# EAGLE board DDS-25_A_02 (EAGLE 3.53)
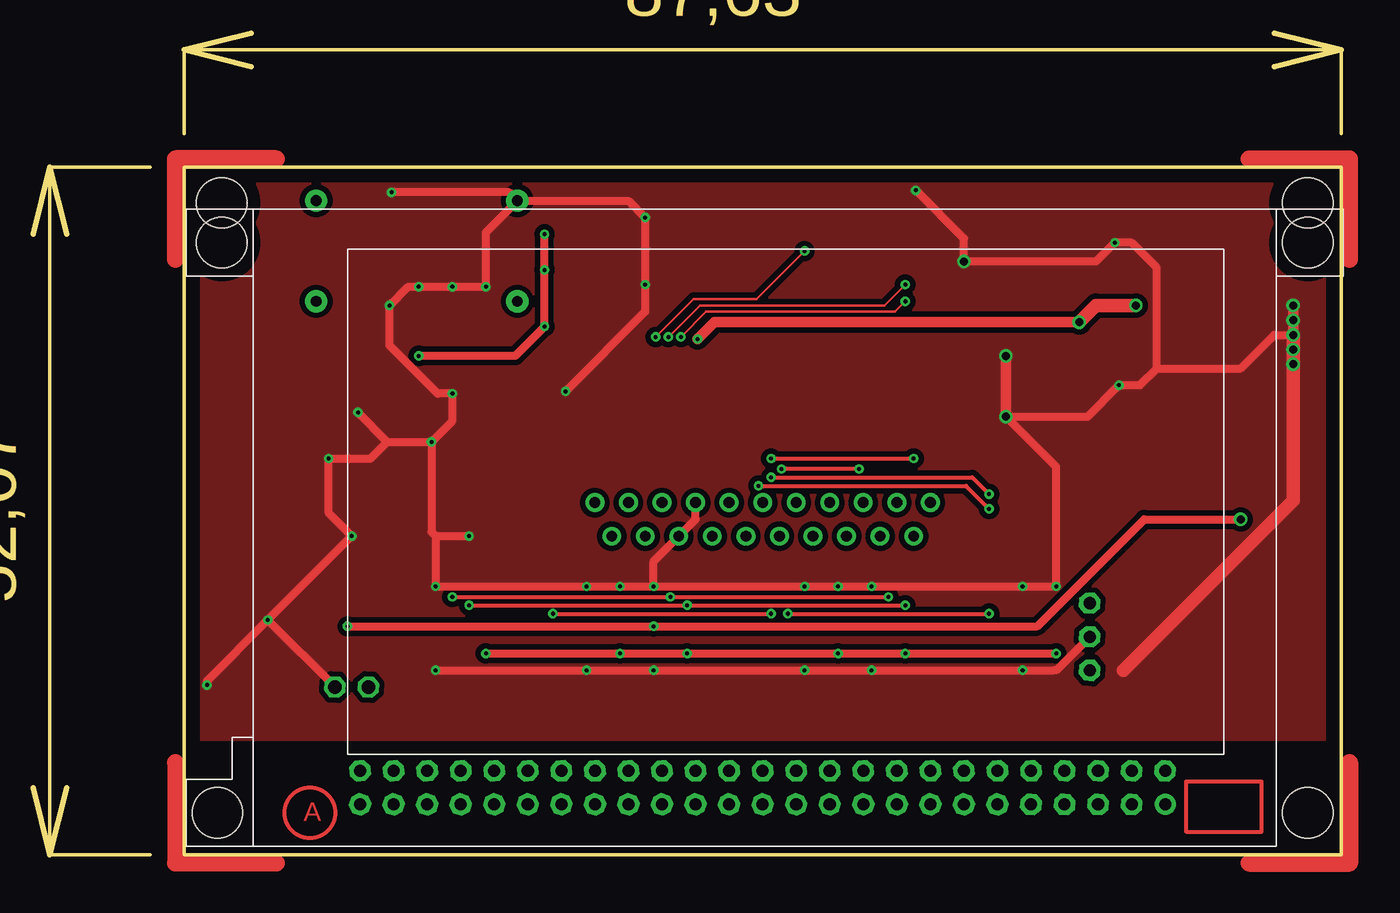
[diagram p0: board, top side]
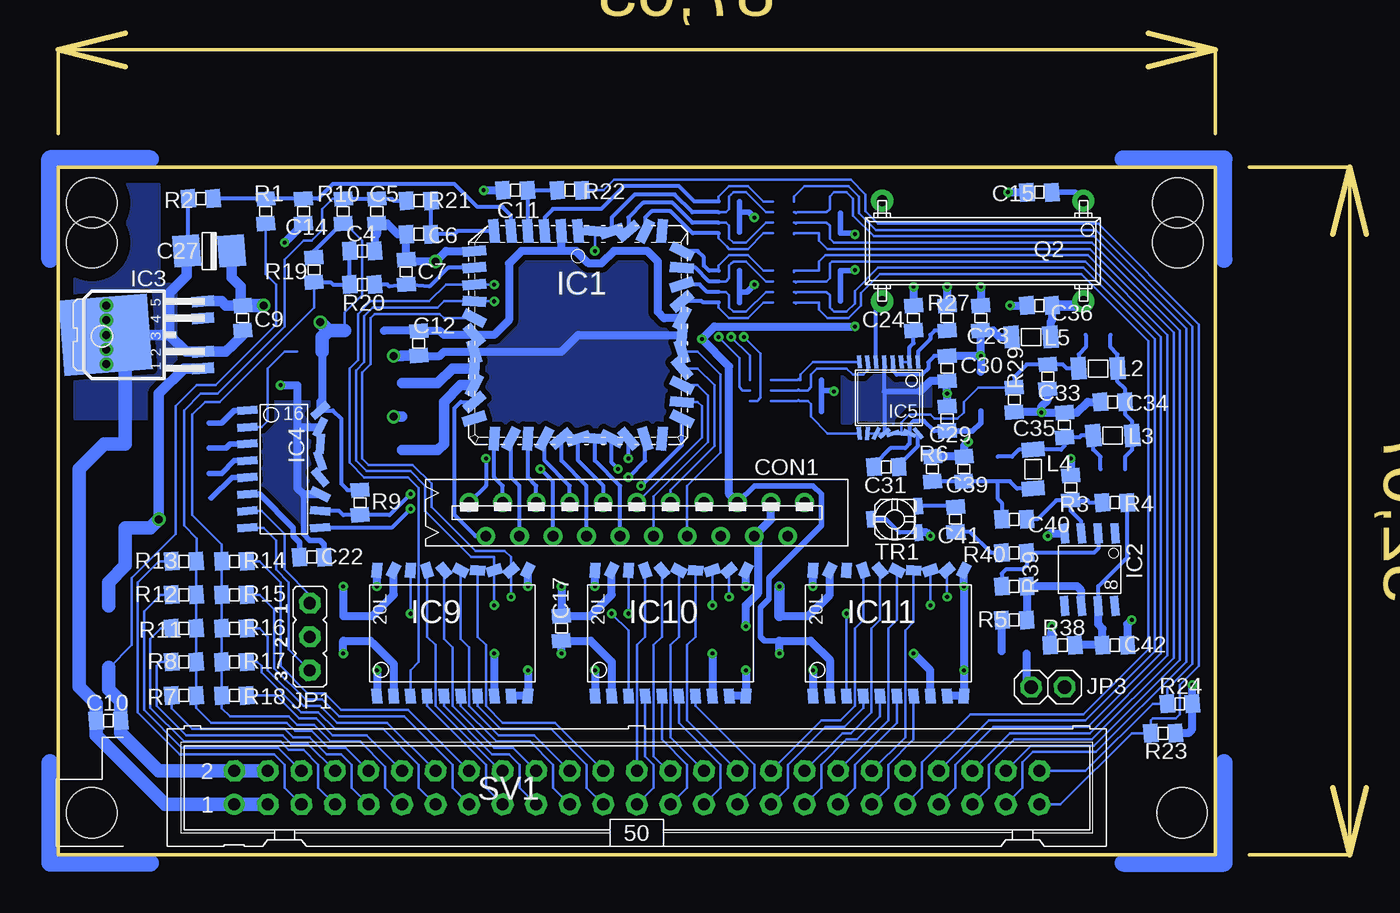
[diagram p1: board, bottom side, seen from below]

Size 99.06 x 62.23 mm. Coordinates in mm from the lower left corner, seen from the top.
Outline: 8.89,0 1.27,0
Outline: 1.27,0 1.27,52.07
Outline: 1.27,52.07 8.89,52.07
Outline: 11.43,54.61 11.43,60.96
Outline: 11.43,60.96 99.06,60.96
Outline: 99.06,60.96 99.06,54.61
Outline: 11.43,60.96 16.51,62.23
Outline: 11.43,60.96 16.51,59.69
Outline: 93.98,62.23 99.06,60.96
Outline: 93.98,59.69 99.06,60.96
Outline: 1.27,52.07 0,46.99
Outline: 1.27,52.07 2.54,46.99
Outline: 1.27,0 0,5.08
Outline: 1.27,0 2.54,5.08
Outline: 11.43,0 99.06,0 99.06,52.07 11.43,52.07 11.43,0
Copper layers used: Top, Bottom

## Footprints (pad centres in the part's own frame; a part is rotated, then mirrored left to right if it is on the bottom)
05' = smd 1.092 x 1.397 rotated 4.4:  0.94,0 | smd 1.092 x 1.397 rotated 4.3:  -0.94,0
28 = smd 2.007 x 2.388 rotated 4.4:  1.702,0 | smd 2.007 x 2.388 rotated 4.3:  -1.702,0
N_21 = drill 0.813 pad 1.422 round:  -1.27,-1.27;  0,1.27;  1.27,-1.27;  2.54,1.27;  3.81,-1.27;  5.08,1.27;  6.35,-1.27;  7.62,1.27;  10.16,1.27;  12.7,1.27;  -2.54,1.27;  -5.08,1.27;  -7.62,1.27;  -10.16,1.27;  -12.7,1.27;  -3.81,-1.27;  -6.35,-1.27;  -8.89,-1.27;  -11.43,-1.27;  8.89,-1.27;  11.43,-1.27
CC44 = smd 0.76 x 1.8 rotated 4.9:  -5.08,-7.86 | smd 0.76 x 1.8 rotated 5:  -3.81,-7.86 | smd 0.76 x 1.8 rotated 4.3:  -2.54,-7.86 | smd 0.76 x 1.8 rotated 26.8:  -1.27,-7.86 | smd 0.76 x 1.8 rotated 49.3:  0,-7.86 | smd 0.76 x 1.8 rotated 71.8:  1.27,-7.86 | smd 0.76 x 1.8 rotated 94.3:  2.54,-7.86 | smd 0.76 x 1.8 rotated 139.5:  -2.54,7.86 | smd 0.76 x 1.8 rotated 117:  -1.27,7.86 | smd 0.76 x 1.8 rotated 94.5:  0,7.86 | smd 0.76 x 1.8 rotated 72:  1.27,7.86 | smd 0.76 x 1.8 rotated 49.5:  2.54,7.86 | smd 0.76 x 1.8 rotated 27:  3.81,7.86 | smd 0.76 x 1.8 rotated 4.5:  5.08,7.86 | smd 1.8 x 0.76 rotated 4.7:  -7.86,-6.35;  -7.86,-5.08 | smd 1.8 x 0.76 rotated 4.5:  -7.86,-2.54 | smd 1.8 x 0.76 rotated 4.4:  -7.86,-1.27;  7.86,-3.81 | smd 1.8 x 0.76 rotated 4.3:  -7.86,0 | smd 1.8 x 0.76 rotated 94.6:  -7.86,1.27 | smd 1.8 x 0.76 rotated 72.1:  -7.86,2.54 | smd 1.8 x 0.76 rotated 49.6:  -7.86,3.81 | smd 1.8 x 0.76 rotated 184.3:  7.86,-6.35 | smd 1.8 x 0.76 rotated 26.9:  7.86,-2.54 | smd 1.8 x 0.76 rotated 49.4:  7.86,-1.27 | smd 1.8 x 0.76 rotated 71.9:  7.86,0 | smd 1.8 x 0.76 rotated 94.4:  7.86,1.27 | smd 1.8 x 0.76 rotated 116.9:  7.86,2.54 | smd 1.8 x 0.76 rotated 139.4:  7.86,3.81 | smd 0.76 x 1.8 rotated 116.8:  3.81,-7.86 | smd 0.76 x 1.8 rotated 139.3:  5.08,-7.86 | smd 0.76 x 1.8 rotated 162:  -3.81,7.86 | smd 0.76 x 1.8 rotated 184.5:  -5.08,7.86 | smd 0.76 x 1.8 rotated 206.9:  6.35,7.86 | smd 1.8 x 0.76 rotated 161.9:  7.86,5.08 | smd 1.8 x 0.76 rotated 184.4:  7.86,6.35 | smd 1.8 x 0.76 rotated 206.8:  7.86,-5.08 | smd 0.76 x 1.8 rotated 161.8:  6.35,-7.86 | smd 1.8 x 0.76 rotated 4.6:  -7.86,-3.81;  -7.86,6.35 | smd 1.8 x 0.76 rotated 27.1:  -7.86,5.08 | smd 0.76 x 1.8 rotated 207:  -6.35,7.86 | smd 0.76 x 1.8 rotated 4.8:  -6.35,-7.86
-8 = smd 0.61 x 1.524 rotated 4.3:  -1.27,-2.743 | smd 0.61 x 1.524 rotated 4.9:  -1.27,2.743 | smd 0.61 x 1.524 rotated 4.4:  0,-2.743 | smd 0.61 x 1.524 rotated 4.5:  1.27,-2.743 | smd 0.61 x 1.524 rotated 4.8:  0,2.743 | smd 0.61 x 1.524 rotated 4.7:  1.27,2.743;  2.54,2.743 | smd 0.61 x 1.524 rotated 4.6:  2.54,-2.743
AC = smd 0.813 x 1.676 rotated 4.3:  -2.54,-3.175 | smd 0.813 x 1.676 rotated 4.4:  -1.27,-3.175 | smd 0.813 x 1.676 rotated 4.6:  1.27,-3.175 | smd 0.813 x 1.676 rotated 4.7:  2.54,-3.175 | smd 5.715 x 6.667 rotated 4.5:  0,4.191
-16 = smd 0.61 x 1.524 rotated 4.3:  -3.81,-2.819;  3.81,2.692 | smd 0.61 x 1.524 rotated 139.3:  -3.81,2.692 | smd 0.61 x 1.524 rotated 4.4:  -2.54,-2.819 | smd 0.61 x 1.524 rotated 4.5:  -1.27,-2.819 | smd 0.61 x 1.524 rotated 116.8:  -2.54,2.692 | smd 0.61 x 1.524 rotated 94.3:  -1.27,2.692 | smd 0.61 x 1.524 rotated 4.6:  0,-2.819 | smd 0.61 x 1.524 rotated 71.8:  0,2.692 | smd 0.61 x 1.524 rotated 4.7:  1.27,-2.819;  2.54,-2.819 | smd 0.61 x 1.524 rotated 49.3:  1.27,2.692 | smd 0.61 x 1.524 rotated 4.8:  3.81,-2.819 | smd 0.61 x 1.524 rotated 26.8:  2.54,2.692 | smd 0.61 x 1.524 rotated 4.9:  5.08,-2.819 | smd 0.61 x 1.524 rotated 5:  5.08,2.692
SOP016 = smd 0.305 x 0.991 rotated 4.3:  -2.235,-3.029;  1.575,2.381 | smd 0.305 x 0.991 rotated 4.4:  -1.6,-3.029 | smd 0.305 x 0.991 rotated 4.5:  -0.965,-3.029 | smd 0.305 x 0.991 rotated 4.6:  -0.33,-3.029 | smd 0.305 x 0.991 rotated 4.7:  0.305,-3.029;  0.94,-3.029 | smd 0.305 x 0.991 rotated 4.8:  1.575,-3.029 | smd 0.305 x 0.991 rotated 4.9:  2.21,-3.029 | smd 0.305 x 0.991 rotated 139.3:  -2.235,2.381 | smd 0.305 x 0.991 rotated 116.8:  -1.6,2.381 | smd 0.305 x 0.991 rotated 94.3:  -0.965,2.381 | smd 0.305 x 0.991 rotated 71.8:  -0.33,2.381 | smd 0.305 x 0.991 rotated 49.3:  0.305,2.381 | smd 0.305 x 0.991 rotated 26.8:  0.94,2.381 | smd 0.305 x 0.991 rotated 5:  2.21,2.381
-20L = smd 0.762 x 1.143 rotated 4.3:  -5.08,-5.131;  6.35,-5.131 | smd 0.762 x 1.143 rotated 4.4:  -3.81,-5.131;  -5.08,4.394 | smd 0.762 x 1.143 rotated 4.5:  -2.54,-5.131 | smd 0.762 x 1.143 rotated 4.6:  -1.27,-5.131 | smd 0.762 x 1.143 rotated 4.7:  0,-5.131;  1.27,-5.131 | smd 0.762 x 1.143 rotated 4.8:  2.54,-5.131 | smd 0.762 x 1.143 rotated 4.9:  3.81,-5.131 | smd 0.762 x 1.143 rotated 5:  5.08,-5.131 | smd 0.762 x 1.143 rotated 49.3:  5.08,4.394 | smd 0.762 x 1.143 rotated 26.8:  6.35,4.369 | smd 0.762 x 1.143 rotated 71.8:  3.81,4.394 | smd 0.762 x 1.143 rotated 94.3:  2.54,4.394 | smd 0.762 x 1.143 rotated 116.8:  1.27,4.394 | smd 0.762 x 1.143 rotated 139.3:  0,4.394 | smd 0.762 x 1.143 rotated 161.8:  -1.27,4.394 | smd 0.762 x 1.143 rotated 184.3:  -2.54,4.394 | smd 0.762 x 1.143 rotated 206.8:  -3.81,4.394
2 = drill 0.914 pad 1.6 octagon:  -2.54,0;  0,0;  2.54,0
02 = drill 1.016 pad 1.6 octagon:  -1.27,0;  1.27,0
06' = smd 1.143 x 1.702 rotated 4.4:  1.473,0 | smd 1.143 x 1.702 rotated 4.3:  -1.473,0
L14P = drill 0.813 pad 1.676 round:  -7.62,3.81;  7.62,3.81;  7.62,-3.81;  -7.62,-3.81
50 = drill 0.914 pad 1.6 round:  -30.48,-1.27 | drill 0.914 pad 1.6 octagon:  -30.48,1.27;  -27.94,-1.27;  -27.94,1.27;  -25.4,-1.27;  -25.4,1.27;  -22.86,-1.27;  -22.86,1.27;  -20.32,-1.27;  -20.32,1.27;  -17.78,-1.27;  -17.78,1.27;  -15.24,-1.27;  -15.24,1.27;  -12.7,-1.27;  -12.7,1.27;  -10.16,-1.27;  -10.16,1.27;  -7.62,-1.27;  -7.62,1.27;  -5.08,-1.27;  -5.08,1.27;  -2.54,-1.27;  -2.54,1.27;  0,-1.27;  0,1.27;  2.54,-1.27;  2.54,1.27;  5.08,1.27;  5.08,-1.27;  7.62,-1.27;  7.62,1.27;  10.16,1.27;  10.16,-1.27;  12.7,-1.27;  12.7,1.27;  15.24,1.27;  15.24,-1.27;  17.78,-1.27;  17.78,1.27;  20.32,-1.27;  20.32,1.27;  22.86,-1.27;  22.86,1.27;  25.4,-1.27;  25.4,1.27;  27.94,-1.27;  27.94,1.27;  30.48,-1.27;  30.48,1.27
15 = smd 1.27 x 0.635 rotated 4.3:  -1,-1.8 | smd 1.27 x 0.635 rotated 4.5:  1,-1.8 | smd 1.27 x 0.635 rotated 4.4:  0,1.8
D = hole 3.81: -42.545,-18.415; 40.005,-18.415; 40.005,24.765; -42.228,24.765; -42.227,27.781; 40.005,27.781

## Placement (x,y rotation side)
C1  3p3  [05]  20.32,39.37 180 bottom
C2  4p7  [05]  19.21,29.21 0 bottom
C3  3p3  [05]  27.94,29.21 90 bottom
C4  10n  [05']  76.04,45.72 0 bottom
C5  10n  [05']  74.93,48.74 270 bottom
C6  10n  [05']  71.75,46.99 180 bottom
C7  10n  [05']  72.71,44.13 90 bottom
C8  100u/16V  [-SMD3]  93.98,27.94 270 bottom
C9  100n  [05']  85.09,40.64 270 bottom
C10  100n  [05']  95.25,10.16 180 bottom
C11  10n  [05']  64.45,50.32 180 bottom
C12  100n  [05']  71.75,38.73 270 bottom
C13  100n  [05]  80.01,35.56 0 bottom
C14  1n  [05']  80.49,48.74 270 bottom
C15  10n  [05']  24.76,50.16 180 bottom
C16  470n  [05]  87.63,31.75 90 bottom
C17  100n  [05']  60.96,17.14 90 bottom
C18  470n  [05]  87.63,27.94 90 bottom
C19  470n  [05]  80.01,38.1 0 bottom
C20  100n  [05]  77.47,17.15 90 bottom
C21  100n  [05]  44.45,17.14 90 bottom
C22  470n  [05']  79.85,22.54 0 bottom
C23  100n  [05']  29.21,40.64 90 bottom
C24  10n  [05']  34.29,40.64 90 bottom
C27  4u7  [28]  87.63,45.72 180 bottom
C29  100n  [05']  31.75,33.02 90 bottom
C30  100n  [05']  31.75,36.83 270 bottom
C31  10n  [05']  36.35,29.37 180 bottom
C33  15p  [05']  24.13,36.2 270 bottom
C34  27p  [05']  19.21,34.29 180 bottom
C35  27p  [05']  22.86,32.54 90 bottom
C36  100n  [05']  24.76,41.59 180 bottom
C39  15p  [05']  30.48,29.21 90 bottom
C40  100n  [05']  26.67,25.4 180 bottom
C41  100n  [05']  31.11,25.4 90 bottom
C42  100n  [05']  19.05,15.88 0 bottom
C43  100n  [05]  26.67,15.24 0 bottom
CA1  10n  [06-4X]  48.26,48.26 270 bottom
CA2  10n  [06-4X]  48.26,43.02 270 bottom
CA3  100p  [06-4X]  42.07,34.77 270 bottom
CON1  120 x 64 Dots  [N_21]  55.24,25.4 0 bottom
D1  S1J  [32]  95.25,16.51 90 bottom
IC1  PIC16F877A  [CC44]  59.69,39.37 270 bottom
IC2  LT1252  [-8]  20.32,21.59 180 bottom
IC3  LF50  [AC]  91.28,39.37 90 bottom
IC4  LMS202  [-16]  81.92,29.84 270 bottom
IC5  AD9835  [SOP016]  36.2,34.29 180 bottom
IC9  TPIC6595DW  [-20L]  69.85,17.15 0 bottom
IC10  TPIC6595DW  [-20L]  53.34,17.14 0 bottom
IC11  TPIC6595DW  [-20L]  36.83,17.15 0 bottom
JP1  JP2E  [2]  80.01,16.51 270 bottom
JP3  1-25MHz  [02]  24.13,12.7 0 bottom
L1  FERIT  [06]  75.88,39.69 180 bottom
L2  2u7  [06']  20.32,36.83 180 bottom
L3  3u3  [06']  19.21,31.75 0 bottom
L4  2u7  [06']  25.24,29.21 90 bottom
L5  FERIT  [06']  25.4,39.21 0 bottom
L7  FERIT  [06]  29.21,35.08 90 bottom
Q1  CRA4000  [RESON2]  73.03,33.18 90 bottom
Q2  50.000 MHz  [L14P]  29.05,45.72 180 bottom
R1  100k  [05']  83.34,48.74 270 bottom
R2  47k  [05']  88.27,49.69 0 bottom
R3  4k7  [05']  22.38,27.78 90 bottom
R4  4k7  [05']  19.05,26.67 180 bottom
R5  47R  [05']  26.67,17.78 0 bottom
R6  330R  [05']  32.86,29.21 90 bottom
R7  10k  [05']  89.53,12.06 0 bottom
R8  6k8  [05']  89.53,14.61 0 bottom
R9  33k  [05']  76.2,26.67 270 bottom
R10  10k  [05']  77.47,48.74 270 bottom
R11  4k7  [05']  89.53,17.14 0 bottom
R12  2k7  [05']  89.53,19.68 0 bottom
R13  680R  [05']  89.53,22.23 0 bottom
R14  10k  [05']  85.73,22.23 180 bottom
R15  6k8  [05']  85.73,19.69 180 bottom
R16  4k7  [05']  85.73,17.15 180 bottom
R17  2k7  [05']  85.73,14.61 180 bottom
R18  680R  [05']  85.73,12.07 180 bottom
R19  10k  [05']  79.69,44.29 90 bottom
R20  1k  [05']  76.04,43.18 0 bottom
R21  1k  [05']  71.75,49.53 0 bottom
R22  1K  [05']  60.33,50.32 180 bottom
R23  100k  [05']  15.4,9.21 180 bottom
R24  100k  [05']  14.13,11.43 180 bottom
R27  3k9  [05']  31.75,40.64 270 bottom
R29  330R  [05']  26.67,34.45 90 bottom
R38  33R  [05']  23.02,15.88 0 bottom
R39  2k2  [05']  26.67,20.32 0 bottom
R40  100R  [05']  26.67,22.86 0 bottom
RA1  1k  [06-4X]  44.13,43.02 90 bottom
RA2  10k  [06-4X]  40.64,43.02 90 bottom
RA3  1k  [06-4X]  44.13,48.26 270 bottom
RA4  10k  [06-4X]  40.64,48.26 270 bottom
RA5  100R  [06-4X]  45.88,34.77 270 bottom
SV1  ML50  [50]  55.24,5.08 0 bottom
TR1  1k  [15]  35.72,25.4 90 bottom
U$1  [D]  56.52,21.59 0 top
U$3  [2']  99.06,52.07 180 top
U$4  [2']  11.43,52.07 270 top
U$5  [2']  99.06,0 90 top
U$6  [2']  11.43,0 0 top

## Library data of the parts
C1-C3 C13 C16 C18-C21 C43 = cap
C4-C7 C9-C12 C14 C15 C17 C22-C24 C27 C29-C31 C33-C36 C39-C42 L2-L4 R1-R24 R27 R29 R38-R40 = SMD
C8 CA1-CA3 D1 L1 L7 Q1 RA1-RA5 = RYKL-dis
CON1 TR1 U$1 = FRANTA  
IC1 = MICROCHI
IC2 = SMD-IC1
IC3 IC9-IC11 = RYKL ic.
IC4 = MAXIM
IC5 = RYKL - I
JP1 = JUMPS
JP3 = PINHEAD
L5 = Kopie - 
Q2 = QUARTZ
SV1 = CON-ML
U$3-U$6 = MARKS

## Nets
+5V: C9. C13. C17. C19. C20. C21. C23. C27. C30. CON1. IC3. IC4. IC5. IC9. IC10. IC11. L1. L5. L7. R9. R10. R19. RA2. RA4.
+12V: C10. D1. R1. SV1.
A0: CON1. IC1.
BT01: R7. SV1.
BT02: R8. SV1.
BT03: R11. SV1.
BT04: R12. SV1.
BT05: R13. SV1.
BT06: C5. R7. R8. R10. R11. R12. R13. R21. SV1.
BT07: R14. SV1.
BT08: R15. SV1.
BT09: R16. SV1.
BT10: R17. SV1.
BT11: R18. SV1.
BT12: C4. R14. R15. R16. R17. R18. R19. R20. SV1.
CLK: IC1. IC9. IC10. IC11. RA5.
CS1\: CON1. IC1.
D0: CON1. IC1.
D1: CON1. IC1.
D2: CON1. IC1.
D3: CON1. IC1.
D4: CON1. IC1.
D5: CON1. IC1.
D6: CON1. IC1.
D7: CON1. IC1.
DATA: IC1. IC9. RA5.
DI01: RA1. RA2. SV1.
DI02: RA1. RA2. SV1.
DI03: RA1. RA2. SV1.
DI04: RA1. RA2. SV1.
DI05: RA3. RA4. SV1.
DI06: RA3. RA4. SV1.
DI07: RA3. RA4. SV1.
GND: C4. C5. C6. C7. C8. C9. C10. C11. C12. C13. C14. C15. C17. C20. C21. C22. C23. C24. C27. C29. C30. C33. C34. C35. C36. C39. C42. CA1. CA2. CA3. CON1. IC1. IC2. IC3. IC4. IC5. IC9. IC10. IC11. JP1. JP3. Q1. Q2. R2. R3. R6. R23. R24. R27. R29. SV1. TR1.
N$1: C3. C39. C40. L4. R6.
N$2: C18. IC4.
N$4: CA2. IC1. RA1.
N$5: C16. IC4.
N$6: C16. IC4.
N$7: CA2. IC1. RA1.
N$8: C18. IC4.
N$9: C19. IC4.
N$10: C22. IC4.
N$11: CA2. IC1. RA1.
N$12: CA2. IC1. RA1.
N$13: C36. L5. Q2.
N$14: IC1. Q1.
N$15: IC1. Q1.
N$16: C40. IC2. R3. R4.
N$17: CA1. IC1. RA3.
N$18: C11. IC1. R22.
N$19: C6. IC1. R21.
N$20: C2. C3. C35. L3. L4.
N$21: C1. C2. C34. L2. L3.
N$22: C41. R40.
N$23: C43. R5.
N$25: C12. IC1. L1.
N$26: C41. TR1.
N$27: CA1. IC1. RA3.
N$29: C15. Q2.
N$31: CA1. IC1. RA3.
N$32: C1. C33. IC5. L2. R29.
N$33: CA3. IC5. RA5.
N$35: CA3. IC5. RA5.
N$36: C7. IC1. R20.
N$42: CA3. IC5. RA5.
N$44: IC9. IC10.
N$46: IC10. IC11.
N$52: CA1. IC1. RA3.
N$69: C29. C31. IC5. L7.
N$71: IC5. Q2.
N$78: C31. IC5.
N$82: IC5. R27.
N$96: C24. IC5.
N$97: C42. IC2. R4. R38.
N$98: IC2. R5. R39.
N$99: IC2. R39. R40.
N$110: C43. JP3.
PWM\: CON1. IC1.
PWRSENSE: C14. IC1. R1. R2.
R1-1: IC9. SV1.
R1-2: IC9. SV1.
R1-3: IC9. SV1.
R1-4: IC9. SV1.
R1-5: IC9. SV1.
R1-6: IC9. SV1.
R1-7: IC9. SV1.
R1-8: IC9. SV1.
R2-1: IC10. SV1.
R2-2: IC10. SV1.
R2-3: IC10. SV1.
R2-4: IC10. SV1.
R2-5: IC10. SV1.
R2-6: IC10. SV1.
R2-7: IC10. SV1.
R2-8: IC10. SV1.
R2IN: IC4. JP1.
R3-1: IC11. SV1.
R3-2: IC11. SV1.
R3-3: IC11. SV1.
R3-4: IC11. SV1.
R3-5: IC11. SV1.
R3-6: IC11. SV1.
R3-7: IC11. SV1.
R3-8: IC11. SV1.
RD\: CON1. IC1.
RES\: CON1. IC1.
RX-LEVEL: R24. RA3. SV1.
RXD: IC1. IC4.
STB1: IC1. IC9. IC10. IC11.
STB2: IC1. RA5.
T2OUT: IC4. JP1.
TX-LEVEL: R22. R23. SV1.
TXD: IC1. IC4. R9.
VCC: C8. CON1. D1. IC3. R38.
WR\: CON1. IC1.

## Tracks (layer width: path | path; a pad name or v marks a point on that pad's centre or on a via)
+5V  (via drill 0.3 pad 0.61, 0.61 pad 1.02)
  Top 0.61: v38.73,46.99 v38.73,44.29 v38.73,40.01 | v38.73,40.01 36.51,37.78 v29.21,37.78 | v34.29,15.24 v44.45,15.24 v49.53,15.24 v60.96,15.24 v66.04,15.24 v77.47,15.24 | v38.73,40.01
  Top 0.813: v50.32,39.05 51.59,40.32 v79.22,40.32
  Top 1.016: v79.22,40.32 80.49,41.59 v83.5,41.59
  Bottom 0.2: 85.08,41.59 C9. | 77.36,39.69 77.36,41.07 76.04,42.39 76.04,46.51 77.32,47.8 77.47,47.8 77.62,47.8 | 79.69,45.72 79.69,45.23 | 76.36,27.62 76.35,27.61 R9. | v38.73,46.99 38.8,47.06 | v38.73,44.29 38.8,44.22 | 39.84,47.86 39.84,47.79 39.85,47.78 39.84,47.78 | 39.84,48.66 39.84,48.58 39.85,48.58 39.84,48.57 | 39.84,43.42 39.84,43.49 39.85,43.5 39.84,43.5 | 39.84,42.62 39.84,42.7 39.85,42.7 39.84,42.71 | 39.84,41.82 39.84,41.9 39.85,41.91 39.84,41.92
  Bottom 0.254: 75.42,16.2 75.25,16.03
  Bottom 0.305: 77.62,47.8 79.69,45.72 | 79.22,33.66 78.26,33.66 77.63,33.02 77.63,28.1 77.15,27.62 76.36,27.62 | C30. 32.72,37.77 33.18,37.31 33.18,36.83 33.66,36.35 35.56,36.35 35.86,36.66 35.86,37.32
  Bottom 0.406: 38.8,47.06 39.84,47.06 39.84,47.78 | 38.8,44.22 39.84,44.22 39.84,43.5 | 39.84,47.86 39.84,48.57 | 39.84,43.42 39.84,42.71 | 39.84,42.62 39.84,41.92 | 29.22,37.77 29.21,37.76 | 44.45,16.2 45.57,16.2 45.88,16.51 45.88,18.73 45.24,19.37 45.24,20.95 41.27,24.92 41.27,27.3 41.91,27.94 46.35,27.94 47.62,26.67 | v50.32,39.05 | 29.21,36.56 | C23.
  Bottom 0.61: 73.66,12.01 73.66,14.45 75.25,16.03 | 75.42,16.2 77.47,16.2 v77.47,15.24 | 57.15,12.01 57.15,14.61 58.75,16.2 C17. v60.96,15.24 | 40.64,12.01 40.64,14.76 42.08,16.2 44.45,16.2 v44.45,15.24 | 79.07,38.1 79.07,35.89 79.06,35.88 79.07,35.86 79.07,35.56 79.07,34.44 79.22,34.29 79.22,33.66 | 47.62,26.67 48.26,27.3 48.26,36.99 | 47.62,26.67 | L5. 27.78,39.21 28.27,39.7 C23. v29.21,37.78 29.22,37.77 C30. | 29.21,37.76 29.21,36.56 | v44.45,15.24 | 33.02,12.01 33.02,13.97 v34.29,15.24 | 49.53,12.22 | 49.53,12.22 49.53,12.01 | v49.53,15.24 49.53,12.22 | v60.96,15.24 | 66.04,12.01 66.04,12.38 v66.04,15.24 | v77.47,15.24 | 48.26,36.99 | 48.26,36.99 v50.32,39.05 49.37,40.01 v38.73,40.01 | 78.58,39.69
  Bottom 0.813: 88.11,41.91 86.68,41.91 86.36,41.59 85.25,41.59 | 85.25,41.59 85.24,41.58 C9. | 85.25,41.59 85.25,43.02 85.93,43.7 C27.
  Bottom 1.016: v83.5,41.59 85.08,41.59 | 78.58,39.69 77.36,39.69 | v79.22,40.32 78.58,39.69 | 79.07,38.1 79.07,39.2 78.58,39.69
+12V
  Bottom 0.2: 95.25,14.13 | 95.25,14.2 95.25,14.13 | 95.25,14.13 93.5,15.88 93.5,20.95 90.17,24.29 90.17,33.97 88.58,35.56 87.15,35.56 82.55,40.16 82.55,43.18 83.34,43.97 83.34,47.8 | 83.34,47.8
  Bottom 1.016: 95.25,13.97 | 95.25,13.97 95.25,14.2 | 95.25,13.97 95.25,12.54 94.31,11.6 C10. 94.31,9.22 91.44,6.35 85.72,6.35 83.19,6.35
A0
  Bottom 0.2: 64.13,24.29 | 64.13,24.13 64.13,24.29
  Bottom 0.305: 64.77,31.51 64.77,28.57 64.13,27.94 64.13,24.29
BT01
  Bottom 0.2: R7. 90.47,11.1 88.9,9.53 81.91,9.53 81.28,8.89 80.01,8.89 78.74,7.62 77.63,7.62 76.84,6.83 76.84,5.08 75.56,3.81
BT02
  Bottom 0.2: R8. 91.28,14.61 91.6,14.29 91.6,11.27 89.38,9.05 82.07,9.05 | 82.07,9.05 | 82.07,9.05 81.44,8.41 80.17,8.41 78.1,6.35
BT03
  Bottom 0.2: 78.1,3.81 79.38,5.08 79.38,6.83 80.49,7.94 81.6,7.94 82.23,8.57 82.39,8.57 | 82.39,8.57 89.53,8.57 92.07,11.11 92.07,16.35 91.28,17.14 R11. | 82.39,8.57
BT04
  Bottom 0.2: 80.65,6.35 82.39,8.1 89.69,8.1 92.55,10.95 92.55,18.41 91.28,19.68 R12.
BT05
  Bottom 0.2: 80.65,3.81 81.91,5.08 81.91,6.83 82.71,7.62 89.85,7.62 93.03,10.79 93.03,20.64 91.44,22.23 R13.
BT06
  Bottom 0.2: 88.58,22.23 88.59,22.23 | 88.58,22.23 88.59,22.21 88.59,19.68 88.74,19.68 88.59,19.54 88.59,17.14 88.58,17.14 88.59,17.13 88.59,14.61 88.59,14.43 88.74,14.29 88.59,14.14 88.59,12.06 88.59,11.12 87.47,10 81.76,10 81.12,9.37 79.85,9.37 78.58,8.1 77.31,8.1 75.56,6.35 | 88.58,22.23 88.58,23.97 89.53,24.92 89.53,33.66 88.26,34.92 87,34.92 81.91,40.01 81.91,45.09 80.49,46.51 79.85,46.51 79.06,47.31 79.06,48.9 78.28,49.68 R10. 77.32,49.68 77.31,49.69 77.3,49.68
  Bottom 0.305: R21. 73.66,49.53 73.81,49.68 C5. 77.3,49.68
BT07
  Bottom 0.2: 84.61,22.23 | 84.61,22.23 R14. | 84.61,22.23 83.82,22.23 82.23,20.64 82.23,14.29 80.17,12.22 78.9,12.22 77.63,10.95 72.55,10.95 67.94,6.35
BT08
  Bottom 0.2: 84.61,19.68 | 84.61,19.68 R15. | 84.61,19.68 83.82,19.68 82.71,18.57 82.71,14.13 80.33,11.75 79.06,11.75 77.79,10.48 72.87,10.48 69.22,6.83 69.22,5.08 67.94,3.81
BT09
  Bottom 0.2: 84.61,17.14 | 84.61,17.14 R16. | 84.61,17.14 83.82,17.14 83.19,16.51 83.19,13.97 80.49,11.27 79.22,11.27 77.95,10 74.14,10 70.48,6.35
BT10
  Bottom 0.2: R17. | R17. 83.98,14.61 83.66,14.29 83.66,13.81 80.65,10.79 79.38,10.79 78.1,9.53 74.45,9.53 71.75,6.83 71.75,5.08 70.48,3.81
BT11
  Bottom 0.2: R18. | R18. 82.55,12.06 80.8,10.32 79.53,10.32 78.26,9.05 75.72,9.05 73.03,6.35
BT12
  Bottom 0.2: 73.03,3.81 74.3,5.08 74.3,6.67 76.2,8.57 78.42,8.57 79.69,9.84 80.96,9.84 81.6,10.48 86.04,10.48 86.66,11.1 86.66,12.06 86.66,14.59 86.68,14.61 86.66,14.61 86.66,17.13 86.68,17.14 86.66,17.14 86.66,19.67 86.68,19.68 86.66,19.68 86.66,22.05 86.68,22.07 86.66,22.08 86.66,22.23 86.66,23.48 88.9,25.72 88.9,33.34 87.95,34.29 86.84,34.29 79.69,41.43 R19. | R20. 76.99,43.18 76.98,43.19
  Bottom 0.305: 76.98,43.19 C4. | R19. 78.44,43.35 78.26,43.18 R20.
CLK  (via drill 0.3 pad 0.61)
  Top 0.2: v49.05,39.21 50.96,41.12 65.25,41.12 v66.04,41.91
  Top 0.305: v66.04,18.89 v49.53,18.89 v33.02,18.89
  Bottom 0.2: 66.04,21.54 | v66.04,18.89 66.04,21.54 | 49.53,21.54 | v49.53,18.89 49.53,21.54 | 33.02,21.54 | v33.02,18.89 33.02,21.54 | 66.04,21.54 | 66.04,21.54 66.04,22.54 67.79,22.54 71.28,26.04 71.28,27.94 72.39,29.05 75.72,29.05 76.52,29.84 76.52,36.67 75.88,37.31 75.88,40.8 75.25,41.43 70.33,41.43 69.85,41.91 67.55,41.91 | 67.55,41.91 | 67.55,41.91 v66.04,41.91 | v49.05,39.21 47.47,37.62 47.47,35.4 47.23,35.17 46.68,35.17
CS1\
  Bottom 0.2: 65.41,26.83 | 65.41,26.67 65.41,26.83
  Bottom 0.305: 66.04,31.51 66.04,28.57 65.41,27.94 65.41,26.83
D0
  Bottom 0.2: 60.33,26.83 | 60.33,26.67 60.33,26.83
  Bottom 0.305: 62.23,31.51 62.23,29.84 60.33,27.94 60.33,26.83
D1
  Bottom 0.2: 59.05,24.29 | 59.05,24.13 59.05,24.29
  Bottom 0.305: 60.96,31.51 60.96,29.84 59.05,27.94 59.05,24.29
D2
  Bottom 0.2: 57.78,26.99 57.78,26.67
  Bottom 0.305: 59.69,31.51 59.69,29.84 57.78,27.94 57.78,26.99
D3
  Bottom 0.2: 56.52,24.45 56.52,24.13
  Bottom 0.305: 58.42,31.51 58.42,29.84 56.52,27.94 56.52,24.45
D4
  Bottom 0.2: 51.83,34.29 50.64,34.29 50.32,33.97 50.32,31.59 55.24,26.67 | 55.24,26.67
D5
  Bottom 0.2: 51.83,35.56 50.64,35.56 49.85,34.77 49.85,31.27 53.98,27.15 53.98,24.45 53.98,24.13
D6
  Bottom 0.2: 51.83,36.83 50.64,36.83 49.37,35.56 49.37,30.96 52.7,27.62 52.7,26.99 52.7,26.67
D7
  Bottom 0.2: 51.44,24.61 | 51.44,24.13 51.44,24.61 | 51.83,38.1 50.64,38.1 48.9,36.35 48.9,30.48 51.44,27.94 51.44,24.61
DATA  (via drill 0.3 pad 0.61)
  Top 0.2: v66.04,43.18 64.45,41.59 50.48,41.59 v48.1,39.21
  Bottom 0.2: 72.39,12.01 | 72.39,12.01 72.39,13.97 71.75,14.61 71.75,27.78 72.55,28.57 | 72.55,28.57 75.88,28.57 76.99,29.69 76.99,36.83 76.36,37.47 76.36,40.96 75.41,41.91 70.96,41.91 69.69,43.18 67.55,43.18 v66.04,43.18 | v66.04,43.18 | 72.55,28.57 | 46.68,35.97 46.68,37.79 v48.1,39.21
DI01
  Bottom 0.2: 34.92,3.81 33.66,5.08 33.66,6.99 30,10.64 21.43,10.64 16.51,15.56 16.51,38.89 21.59,43.97 36.83,43.97 38.26,42.55 38.26,41.59 39.21,40.64 40.8,40.64 41.44,41.28 41.44,41.82 43.11,41.82 43.18,41.75 43.25,41.82 43.33,41.82
DI02
  Bottom 0.2: 32.38,6.35 28.57,10.16 21.27,10.16 16.03,15.4 16.03,39.05 21.43,44.45 36.99,44.45 38.73,42.7 38.73,41.75 39.37,41.12 40.32,41.12 40.48,41.27 | 43.33,42.62 43.26,42.62 43.18,42.55 43.1,42.62 41.44,42.62 40.88,42.62 40.64,42.39 40.64,41.43 40.48,41.27 | 40.48,41.27
DI03
  Bottom 0.2: 32.38,3.81 31.11,5.08 31.11,6.83 28.26,9.68 21.11,9.68 15.56,15.24 15.56,39.21 21.27,44.93 40.48,44.93 40.64,44.77 40.64,43.66 40.88,43.42 41.44,43.42 43.1,43.42 43.18,43.34 43.26,43.42 43.33,43.42
DI04
  Bottom 0.2: 29.84,6.35 26.99,9.21 20.95,9.21 15.08,15.08 15.08,39.37 21.11,45.4 40.96,45.4 41.44,44.92 41.44,44.22 43.25,44.22 43.33,44.14 | 43.33,44.14 43.34,44.13 | 43.33,44.14 43.33,44.22
DI05
  Bottom 0.2: 29.84,3.81 | 29.84,3.81 28.57,5.08 28.57,6.83 26.67,8.73 20.8,8.73 14.61,14.92 14.61,39.53 20.95,45.88 40.8,45.88 41.44,46.52 41.44,47.06 43.27,47.06 43.33,47 | 43.33,47 43.34,46.99 | 43.33,47 43.33,47.06
DI06
  Bottom 0.2: 43.33,47.86 43.26,47.86 43.18,47.78 43.1,47.86 41.44,47.86 40.88,47.86 40.64,47.62 40.64,46.67 40.32,46.35 20.8,46.35 14.13,39.69 14.13,14.76 20.64,8.26 25.4,8.26 27.3,6.35 | 27.3,6.35
DI07
  Bottom 0.2: 27.3,3.81 26.04,5.08 26.04,6.99 25.24,7.78 20.48,7.78 13.65,14.61 13.65,39.85 20.64,46.83 37.31,46.83 38.89,48.42 38.89,49.69 39.37,50.16 40.32,50.16 40.64,49.85 40.64,48.9 40.88,48.66 41.44,48.66 43.1,48.66 43.18,48.58 43.26,48.66 43.33,48.66
GND  (via drill 0.3 pad 0.61, 0.61 pad 1.02)
  Top 0.2: 36.67,49.53
  Top 0.61: 85.09,36.83 85.09,44.45 83.19,46.35 v81.91,46.35 80.49,44.93 v70.48,44.93 70.48,46.67 v66.83,50.32 | 85.09,36.83 83.82,35.56 v82.23,35.56 79.85,33.18 v73.66,33.18 77.47,29.37 v77.47,20.32 v74.93,20.32 v63.5,20.32 v60.96,20.32 v58.42,20.32 v46.99,20.32 | 85.09,36.83 91.44,36.83 93.98,39.37 v95.41,39.37 | 36.67,49.53 45.09,49.53 v46.35,48.26 v46.35,43.18 46.35,41.12 v40.32,35.08 | 36.67,49.53 34.29,47.15 v34.29,43.02 v31.75,43.02 v29.21,43.02 28.42,43.02 v26.99,41.59 26.99,38.58 30.64,34.92 v31.75,34.92 31.75,32.86 v30.16,31.27 | 26.83,31.27 v24.61,33.5 | 26.83,31.27 v30.16,31.27 | 26.83,31.27 25.56,30 v22.38,30 22.38,25.88 v24.13,24.13 v17.78,17.78 | 30.48,24.13 v33.02,24.13 | 30.48,24.13 30.16,24.45 v30.16,31.27 | v27.15,50.16 36.04,50.16 36.67,49.53 | 30.48,24.13 v30.48,20.32 v41.91,20.32 v44.45,20.32 v46.99,20.32 | v17.78,17.78 JP3. | 50.16,26.67 50.16,25.4 48.9,24.13 46.99,22.23 v46.99,20.32 | v30.48,13.97 v41.91,13.97 v46.99,13.97 v58.42,13.97 v63.5,13.97 v74.93,13.97 77.31,13.97 | 77.47,13.97 80.01,16.51 | v13.18,12.86 13.18,13.18 v17.78,17.78
  Top 0.813: v73.66,33.18 v73.66,37.78 | v95.41,39.37 v95.41,40.48 v95.41,41.59
  Top 1.016: v95.41,39.37 v95.41,38.26 v95.41,37.15 95.41,26.83 82.55,13.97
  Bottom 0.2: 89.38,45.72 | 89.33,45.72 89.38,45.72 | 89.38,45.72 89.21,45.89 | 72.55,44.93 72.56,44.91 72.71,45.07 | 72.71,46.83 72.69,46.84 72.69,46.99 | 80.49,27.15 | 80.49,27.3 80.49,27.15 | 47.46,48.66 47.46,48.58 47.47,48.58 | 47.46,47.86 47.46,47.79 47.47,47.78 | 47.46,47.06 47.46,47.14 47.47,47.15 47.46,47.16 | 47.46,43.42 47.46,43.49 47.47,43.5 47.46,43.5 | 47.46,42.62 47.46,42.55 47.47,42.55 47.46,42.54 | 36.5,31.91 35.86,31.91 | 37.13,31.91 37.15,31.91 | 37.78,31.91 37.77,31.91 | 37.13,31.91 37.78,31.91 | 37.78,31.91 | 24.59,33.48 v24.61,33.5 v24.62,33.51 | 36.5,31.91 | 37.13,31.91 | 36.5,31.91 37.13,31.91 | 36.5,35.08 36.51,35.08 36.5,35.07 | 37.47,25.4 | 37.47,25.4 TR1. | 65.39,50.32 | 29.21,41.58
  Bottom 0.305: 67.31,38.1 | 67.55,38.1 67.31,38.1 | 73.66,21.43 | 73.66,21.43 73.66,21.54 | 57.15,21.43 | 57.15,21.43 57.15,21.54 | 40.64,21.59 | 40.64,21.59 40.64,21.54 | 89.21,45.89 R2. | 36.5,35.08 36.5,37.32 | 36.5,35.07 36.5,31.91 | 33.92,24.4 35.35,24.4 36.35,25.4 37.47,25.4 | 44.45,19.68
  Bottom 0.406: 78.91,22.54 78.91,23.51 79.22,23.81 80.01,23.81 80.49,24.29 80.49,27.15 | 47.46,49.46 47.46,48.66 46.76,48.66 v46.35,48.26 | 47.46,48.58 47.46,47.86 47.46,47.16 | v46.35,43.18 46.91,42.62 47.46,42.62 47.46,43.42 | 47.46,43.5 47.46,44.22 | 47.46,42.54 47.46,41.82 | 33.81,35.08 36.5,35.08 | 41.27,33.57 41.27,34.28 41.27,34.29 41.27,34.3 41.27,34.37 41.27,34.44 41.27,34.45 41.27,35.17 | 41.27,35.17 40.41,35.17 v40.32,35.08 | 41.27,35.97 41.27,35.88 41.27,35.87 41.27,35.17
  Bottom 0.61: 73.66,21.43 73.66,19.68 75.26,18.09 77.47,18.09 v77.47,20.32 | 57.15,21.43 57.15,19.68 58.75,18.09 60.96,18.09 v60.96,20.32 | 44.45,18.09 42.24,18.09 40.64,19.68 40.64,21.59 | 72.69,46.99 73.34,46.99 74.15,47.8 74.93,47.8 74.93,46.99 75.1,46.82 75.1,45.72 | IC1. 69.69,45.72 v70.48,44.93 72.55,44.93 | 72.71,45.07 72.71,46.83 | 67.55,38.1 69.85,38.1 70.17,37.78 71.44,37.78 71.45,37.8 71.75,37.8 | 79.22,32.38 | 80.95,32.38 80.95,35.56 v82.23,35.56 | 80.95,32.38 79.22,32.38 | 79.22,27.3 80.49,27.3 80.95,27.77 80.95,32.38 | v82.23,35.56 | 80.49,47.8 80.49,47.78 v81.91,46.35 | v66.83,50.32 65.39,50.32 | 51.83,39.37 59.69,39.37 60.96,38.1 67.31,38.1 | v29.21,43.02 29.21,41.58 | v29.21,43.02 | v31.75,43.02 R27. | v31.75,43.02 | v34.29,43.02 34.29,41.58 | v34.29,43.02 | 25.7,41.59 v26.99,41.59 | 20.15,34.29 21.11,34.29 21.92,33.48 22.86,33.48 24.59,33.48 | v24.62,33.51 R29. | v24.61,33.5 24.61,33.97 24.13,34.45 24.13,35.26 | v30.16,31.27 30.48,30.96 30.48,30.15 32.72,30.15 32.86,30 | 32.86,30 | 32.86,30 32.86,30.15 | v31.75,34.92 31.75,35.89 33.01,35.89 33.81,35.08 | v31.75,34.92 | v31.75,34.92 31.75,33.96 | v22.38,30 22.38,28.72 | v22.38,30 | 18.11,15.88 18.11,17.45 v17.78,17.78 | 22.86,24.33 23.93,24.33 v24.13,24.13 | 33.92,24.4 33.29,24.4 v33.02,24.13 | v27.15,50.16 25.7,50.16 | v30.48,20.32 30.48,21.51 | v30.48,20.32 | v30.48,13.97 30.48,12.01 31.64,12.01 31.75,11.91 | v30.48,13.97 | v30.48,20.32 v30.48,13.97 | 31.75,11.91 | 31.75,11.91 31.75,12.01 | v41.91,20.32 IC11. | v41.91,20.32 | v46.99,20.32 46.99,21.51 | v46.99,20.32 | v58.42,20.32 IC10. | v58.42,20.32 | v63.5,20.32 63.5,21.51 | v63.5,20.32 | v60.96,20.32 | v74.93,20.32 IC9. 74.93,21.43
  Bottom 0.61: v74.93,20.32 | v77.47,20.32 | v41.91,13.97 41.91,12.01 | v41.91,13.97 | 46.99,12.06 | 46.99,12.06 46.99,12.01 v46.99,13.97 | 48.26,12.01 47.04,12.01 46.99,12.06 | v46.99,13.97 | 63.5,12.06 | 63.5,12.06 63.5,12.01 v63.5,13.97 | 64.77,12.01 63.55,12.01 63.5,12.06 | v63.5,13.97 | v58.42,13.97 58.42,12.01 | v58.42,13.97 | v74.93,13.97 74.93,12.01 | v74.93,13.97 | R23. 13.49,9.21 13.19,9.51 R24. 13.19,12.85 v13.18,12.86
  Bottom 0.813: 44.45,18.09 44.45,19.68 v44.45,20.32 | 85.88,38.58 86.36,38.1 88.11,38.1 89.38,38.1 90.65,39.37 | v95.41,39.37 90.65,39.37 | 85.88,38.58 | 85.09,39.7 85.09,39.37 85.88,38.58 | 89.33,45.72 89.33,43.86 90.65,42.55 90.65,39.37 | 71.75,37.8 73.01,37.8 73.03,37.78 v73.66,37.78 | v73.66,33.18 73.03,33.18 | v44.45,20.32
  Bottom 1.016: 83.19,3.81 85.72,3.81 90.96,3.81 96.19,9.04 96.19,10.16 96.19,11.42 97.47,12.7 97.47,29.21 95.57,31.11 93.98,31.11 93.98,35.56 | 93.98,35.56 | IC3. v95.41,39.37 93.98,37.94 93.98,35.56
  pour Top (isolate 0.406, no thermals): 12.7,50.8 97.79,50.8 97.79,8.73 12.7,8.73
  pour Bottom (isolate 0.406, no thermals): 52.07,31.75 67.31,31.75 67.31,46.99 52.07,46.99
  pour Bottom (isolate 0.406, no thermals): 33.02,36.51 33.02,32.7 39.69,32.7 39.69,36.51
  pour Bottom (isolate 0.406, no thermals): 97.79,50.8 97.79,33.02 90.17,33.02 90.17,43.18 91.44,43.18 91.44,50.8
  pour Bottom (isolate 0.406, no thermals): 80.01,34.29 80.01,24.77 83.82,24.77 83.82,34.29 83.66,34.29
N$1
  Bottom 0.2: 30.48,28.26 | 30.48,28.26 C39. | 30.47,28.27 30.48,28.26 | R6. 32.72,28.27 32.7,28.26 32.69,28.27
  Bottom 0.305: 27.94,28.27 27.94,26.99 27.61,26.66 27.61,25.4 | 27.94,28.27 30.47,28.27 | C39. 32.69,28.27 | L4. 26.47,27.74 27,28.27 27.94,28.27
N$2
  Bottom 0.2: 87.46,27 87.63,27 | 84.77,28.57 84.74,28.57
  Bottom 0.406: 87.46,27 85.88,28.57 84.77,28.57
N$4
  Bottom 0.2: 51.75,41.91 51.83,41.91 | 49.06,41.82 49.06,41.44 48.26,40.64 46.83,40.64 45.65,41.82 44.93,41.82
  Bottom 0.305: 49.06,41.82 50.23,41.82 50.32,41.91 51.75,41.91
N$5
  Bottom 0.2: 84.93,31.11 | 84.74,31.11 84.93,31.11
  Bottom 0.406: 87.63,30.81 86.35,30.81 86.04,31.11 84.93,31.11
N$6
  Bottom 0.2: 84.93,33.66 | 84.93,33.66 84.74,33.66
  Bottom 0.406: 87.63,32.69 86.69,32.69 85.72,33.66 84.93,33.66
N$7
  Bottom 0.2: 51.59,43.18 | 51.59,43.18 51.83,43.18 | 49.06,42.62 48.49,42.62 48.26,42.39 48.26,41.43 47.94,41.12 46.99,41.12 45.48,42.62 44.93,42.62
  Bottom 0.305: 49.06,42.62 49.92,42.62 50.48,43.18 51.59,43.18
N$8
  Bottom 0.2: 84.93,29.84 | 84.74,29.84 84.93,29.84
  Bottom 0.406: 87.63,28.88 86.69,28.88 85.72,29.84 84.93,29.84
N$9
  Bottom 0.2: 80.95,38.1 81.91,38.1 83.19,36.83 83.19,32.86 83.66,32.38 84.46,32.38 | 84.46,32.38 | 84.74,32.38 84.46,32.38
N$10
  Bottom 0.2: 84.46,27.3 | 84.46,27.3 84.74,27.3
  Bottom 0.406: C22. 80.79,23.64 81.28,24.13 81.28,24.77 83.82,27.3 84.46,27.3
N$11
  Bottom 0.2: 49.06,43.42 48.49,43.42 48.26,43.66 48.26,44.61 48.1,44.77 | 48.1,44.77 | 48.1,44.77 47.94,44.93 46.99,44.93 45.48,43.42 44.93,43.42
  Bottom 0.305: 51.83,44.45 50.8,44.45 49.77,43.42 49.06,43.42
N$12
  Bottom 0.2: 44.93,44.22 45.65,44.22 46.83,45.4 48.26,45.4 49.06,44.6 49.06,44.22
  Bottom 0.305: 51.83,45.72 50.64,45.72 50.16,45.24 50.16,44.61 49.78,44.22 49.06,44.22
N$13
  Bottom 0.2: 21.43,41.91
  Bottom 0.61: C36. 23.82,40.49 23.81,40.48 23.93,40.37 23.93,39.21
  Bottom 0.813: C36. 21.75,41.59 21.43,41.91
N$14
  Bottom 0.813: 67.55,36.83 69.22,36.83 70.33,35.72 73.03,35.72
N$15
  Bottom 0.813: 67.55,35.56 68.58,35.56 69.85,34.29 69.85,31.11 70.33,30.64 73.03,30.64
N$16
  Bottom 0.2: 21.59,24.61 | 21.59,24.33 21.59,24.61 | 25.72,25.4 C40.
  Bottom 0.305: R3. 21.13,26.84 20.95,26.67 19.99,26.67 | R3. 22.38,26.04 21.59,25.24 21.59,24.61 | R3. 23.48,26.84 24.92,25.4 25.72,25.4
N$17
  Bottom 0.2: 62.23,47.47 | 62.23,47.47 62.23,47.23 | 49.06,49.46 49.06,49.84 48.26,50.64 46.83,50.64 45.65,49.46 44.93,49.46
  Bottom 0.305: 49.06,49.46 50.89,49.46 52.07,50.64 56.2,50.64 57.94,48.9 61.59,48.9 62.23,48.26 62.23,47.47
N$18
  Bottom 0.2: 63.34,50.32 | 63.34,50.32 C11. | 63.34,50.32 | C11. | C11.
  Bottom 0.305: 63.34,50.32 61.27,50.32 | 63.5,47.23 C11.
N$19
  Bottom 0.2: 70.81,49.53 70.81,49.38 70.8,49.37 70.81,49.36
  Bottom 0.305: 66.04,47.23 68.82,47.23 69.06,46.99 C6. 70.81,49.36
N$20
  Bottom 0.305: 20.15,29.21 20.15,30.15 20.68,30.68 L3. 21.59,31.75 21.74,31.6 C35. 22.86,30.96 23.13,30.68 25.24,30.68 26.31,30.68 26.84,30.15 27.94,30.15
N$21
  Bottom 0.305: 19.38,39.37 19.38,38.43 18.85,37.9 L2. 18.85,35.83 18.27,35.26 C34. 18.27,33.35 17.74,32.82 17.74,31.75 17.74,30.68 18.27,30.15 18.27,29.21
N$22
  Bottom 0.305: R40. 28.42,22.86 30.02,24.46 C41.
N$23
  Bottom 0.2: 27.61,15.24 27.61,15.39 27.62,15.4 27.61,15.41
  Bottom 0.61: 27.61,15.41 R5.
N$25
  Bottom 0.61: 74.41,39.69 71.91,39.69 71.9,39.67 C12. 70.16,39.67 69.85,39.37 67.79,39.37 | 67.79,39.37 | 67.79,39.37 67.55,39.37 66.04,39.37 64.93,40.48 64.93,44.77 63.98,45.72 60.96,45.72 | 60.96,46.83 | 60.96,46.83 60.96,47.23 | 60.96,45.72 60.96,46.83 | 51.83,40.64 53.18,40.64 53.66,41.12 53.66,44.93 54.45,45.72 56.99,45.72 57.94,44.77 58.9,44.77 59.85,45.72 60.96,45.72
N$26
  Bottom 0.2: 31.11,26.34 31.26,26.34 31.32,26.4
  Bottom 0.305: 31.32,26.4 33.92,26.4
N$27
  Bottom 0.2: 54.61,47.47 | 54.61,47.47 54.61,47.23 | 49.06,47.06 49.06,46.68 48.42,46.04 | 48.42,46.04 | 48.42,46.04 48.26,45.88 46.83,45.88 45.65,47.06 44.93,47.06
  Bottom 0.305: 49.06,47.06 51.03,47.06 52.7,48.74 54.13,48.74 54.61,48.26 54.61,47.47
N$29
  Bottom 0.2: Q2.
  Bottom 0.406: C15. 22.07,50.16 Q2.
N$30
  Top 0.305: 87.31,1.75 87.31,5.56 93.03,5.56 93.03,1.75 87.31,1.75
N$31
  Bottom 0.2: 55.88,47.47 | 55.88,47.47 55.88,47.23 | 49.06,47.86 48.49,47.86 48.26,47.62 48.26,46.67 47.94,46.35 46.99,46.35 45.48,47.86 44.93,47.86
  Bottom 0.305: 49.06,47.86 51.03,47.86 52.55,49.37 54.77,49.37 55.88,48.26 55.88,47.47
N$32
  Bottom 0.2: 35.23,31.91 35.23,32.72 34.61,33.34 33.02,33.34 32.7,33.02 30.96,33.02 30.48,33.5 30.48,34.29 29.38,35.39 26.67,35.39 26.67,35.72 | 26.67,35.72
  Bottom 0.305: 26.67,35.72 26.67,36.2 25.73,37.13 C33. 23.01,37.13 22.7,36.83 21.79,36.83 21.79,37.9 21.26,38.43 21.26,39.37
N$33
  Bottom 0.2: 45.08,35.17 43.1,35.17 43.02,35.24 42.95,35.17 42.87,35.17 42.3,35.17 42.07,35.4 42.07,36.35 41.59,36.83 39.37,36.83 38.89,36.35 38.1,36.35 37.77,36.68 37.77,37.32
N$35
  Bottom 0.2: 45.08,35.97 43.09,35.97 43.02,36.04 42.95,35.97 42.87,35.97 42.87,36.03 42.86,36.04 42.86,36.35 41.9,37.32 38.41,37.32
N$36
  Bottom 0.305: 75.1,43.18 74.14,43.18 73.99,43.03 C7. 70.95,43.03 69.53,44.45 67.55,44.45
N$42
  Bottom 0.2: 45.08,34.37 43.1,34.37 43.02,34.45 42.94,34.37 42.87,34.37 42.3,34.37 42.07,34.13 42.07,33.18 40.8,31.91 IC5.
N$44  (via drill 0.3 pad 0.61)
  Top 0.305: v57.15,18.26 v72.39,18.26
  Bottom 0.2: 55.88,12.01 55.88,16.99 v57.15,18.26 | 72.39,21.27 | 72.39,21.27 72.39,21.54 | v72.39,18.26 72.39,21.27
N$46  (via drill 0.3 pad 0.61)
  Top 0.305: v39.37,18.26 v55.88,18.26
  Bottom 0.2: 55.88,21.43 | 55.88,21.43 55.88,21.54 | v55.88,18.26 55.88,21.43 | 39.37,12.01 39.37,12.38 v39.37,18.26
N$52
  Bottom 0.2: 57.15,47.47 | 57.15,47.47 57.15,47.23 | 49.06,48.66 48.49,48.66 48.26,48.9 48.26,49.85 48.1,50.01 | 48.1,50.01 | 48.1,50.01 47.94,50.16 46.99,50.16 45.48,48.66 44.93,48.66
  Bottom 0.305: 49.06,48.66 51.04,48.66 52.39,50.01 55.4,50.01 57.15,48.26 57.15,47.47
N$69
  Bottom 0.2: 37.31,29.53 37.29,29.52 37.29,29.37
  Bottom 0.305: C29. 32.72,32.08 33.5,32.86 34.29,32.86 34.59,32.56 34.59,31.91 34.59,31.13 34.92,30.8 36.04,30.8 37.31,29.53
  Bottom 0.406: 29.21,33.61 29.21,32.7 29.83,32.08 C29.
N$71
  Bottom 0.2: 36.67,41.91
  Bottom 0.305: 37.13,37.32 37.13,41.45 36.67,41.91
N$78
  Bottom 0.2: C31. 35.41,29.52
  Bottom 0.305: 33.96,31.91 33.96,30.97 35.41,29.52
N$82
  Bottom 0.305: 31.75,39.7 32.69,39.7 33.02,39.37 33.02,39.05 33.96,38.11 33.96,37.32
N$96
  Bottom 0.2: 34.59,37.32 34.61,37.31 34.62,37.32 35.23,37.32 | 34.59,37.32 | 34.29,39.53 | 34.29,39.53 C24.
  Bottom 0.305: 34.59,37.32 34.59,38.43 34.29,38.73 34.29,39.53
N$97
  Bottom 0.305: 20.32,18.85 20.32,20.32 18.11,22.53 R4.
  Bottom 0.61: 20.16,15.88 | 20.16,15.88 C42. 19.99,17.13 20.32,17.46 20.32,18.57 | 20.16,15.88 22.08,15.88 | 20.32,18.57 | 20.32,18.57 20.32,18.85
N$98
  Bottom 0.2: 21.59,19.05 | 21.59,18.85 21.59,19.05 | 25.73,17.78 25.73,17.93 25.72,17.94 25.73,17.95
  Bottom 0.61: 21.59,19.05 21.59,20 21.91,20.32 25.73,20.32 25.73,17.95
N$99
  Bottom 0.2: 20.32,24.13 | 20.32,24.33 20.32,24.13
  Bottom 0.305: 20.32,24.13 20.32,23.18 20.64,22.86 25.73,22.86 25.73,21.89 26.04,21.59 27.3,21.59 27.61,21.29 R39.
N$110
  Bottom 0.61: 25.73,15.24 25.73,13.03 25.4,12.7
PWM\  (via drill 0.3 pad 0.61)
  Top 0.305: v55.88,30 v66.67,30
  Bottom 0.2: v55.88,30 | 67.94,26.67
  Bottom 0.305: v55.88,30 55.88,31.51 | v66.67,30 66.67,27.94 67.94,26.67
PWRSENSE
  Bottom 0.2: R1. 83.2,49.68 83.19,49.69 83.17,49.68 | 87.15,49.69 | 87.15,49.69 87.32,49.69 | 87.14,49.68 87.15,49.69 | 64.77,47.47 | 64.77,47.23 64.77,47.47
  Bottom 0.305: 83.17,49.68 C14. 79.39,49.68 78.26,50.8 69.06,50.8 67.31,49.05 65.41,49.05 64.77,48.42 64.77,47.47 | R1. 87.14,49.68
R1-1
  Bottom 0.2: 65.41,3.81 66.67,5.08 66.67,6.83 71.12,11.27 71.12,12.01 | 71.12,12.01
R1-2
  Bottom 0.2: 69.85,12.01 69.85,11.27 66.2,7.62 64.93,7.62 64.13,6.83 64.13,5.08 62.87,3.81
R1-3
  Bottom 0.2: 68.58,12.01 68.58,11.27 65.88,8.57 63.34,8.57 61.59,6.83 61.59,5.08 60.33,3.81
R1-4
  Bottom 0.2: 67.31,12.01 67.31,11.27 65.56,9.53 61.75,9.53 59.05,6.83 59.05,5.08 57.78,3.81
R1-5
  Bottom 0.2: 57.78,6.35 61.44,10 65.41,10 66.67,11.27 66.67,15.88 67.31,16.51 67.31,21.11 | 67.31,21.11 | 67.31,21.11 67.31,21.54
R1-6
  Bottom 0.2: 68.58,21.54 68.58,16.35 67.94,15.72 67.94,11.27 65.72,9.05 63.02,9.05 60.33,6.35
R1-7
  Bottom 0.2: 69.85,21.54 69.85,16.35 69.22,15.72 69.22,11.27 66.04,8.1 64.61,8.1 62.87,6.35
R1-8
  Bottom 0.2: 71.12,21.54 71.12,16.51 70.48,15.88 70.48,11.27 65.56,6.35 65.41,6.35
R2-1
  Bottom 0.2: 54.61,12.01 54.61,7.46 53.98,6.83 53.98,5.08 55.24,3.81 | 55.24,3.81
R2-2
  Bottom 0.2: 53.34,12.01 53.34,8.73 51.44,6.83 51.44,5.08 52.7,3.81 | 52.7,3.81
R2-3
  Bottom 0.2: 52.07,12.01 52.07,10 48.9,6.83 48.9,5.08 50.16,3.81 | 50.16,3.81
R2-4
  Bottom 0.2: 50.8,12.01 50.8,11.27 46.35,6.83 46.35,5.08 47.62,3.81
R2-5
  Bottom 0.2: 50.8,21.54 50.8,16.51 51.44,15.88 51.44,10.16 47.62,6.35
R2-6
  Bottom 0.2: 52.07,21.54 52.07,16.51 52.7,15.88 52.7,8.89 50.16,6.35
R2-7
  Bottom 0.2: 53.34,21.54 53.34,16.51 53.98,15.88 53.98,7.46 52.86,6.35 52.7,6.35
R2-8
  Bottom 0.2: 54.61,21.54 54.61,16.51 55.24,15.88 55.24,6.35
R2IN
  Bottom 0.2: 84.74,24.77 84.73,24.77 83.5,24.77 82.55,23.81 82.55,21.59 81.6,20.64 81.6,15.56 JP1.
R3-1
  Bottom 0.2: 38.1,12.01 38.1,11.11 39.53,9.68 40.96,9.68 43.81,6.83 43.81,5.08 45.09,3.81
R3-2
  Bottom 0.2: 36.83,12.01 36.83,10.48 38.58,8.73 39.37,8.73 41.27,6.83 41.27,5.08 42.55,3.81 | 42.55,3.81
R3-3
  Bottom 0.2: 35.56,12.01 35.56,10 38.73,6.83 38.73,5.08 40,3.81 | 40,3.81
R3-4
  Bottom 0.2: 34.29,12.01 34.29,8.73 36.2,6.83 36.2,5.08 37.47,3.81 | 37.47,3.81
R3-5
  Bottom 0.2: 34.29,17.62 34.29,21.54 | 37.47,6.35 34.92,8.89 34.92,16.99 34.29,17.62 | 34.29,17.62
R3-6
  Bottom 0.2: 35.56,21.54 35.56,17.78 36.2,17.14 36.2,10.16 40,6.35
R3-7
  Bottom 0.2: 36.83,21.54 36.83,17.78 37.47,17.14 37.47,10.79 39.05,9.21 39.69,9.21 42.55,6.35 | 42.55,6.35
R3-8
  Bottom 0.2: 38.1,21.54 38.1,17.78 38.73,17.14 38.73,11.27 39.85,10.16 41.27,10.16 45.09,6.35 | 45.09,6.35
RD\  (via drill 0.3 pad 0.61)
  Top 0.305: v62.55,29.21 v56.67,29.21
  Bottom 0.2: 61.59,24.45 61.59,24.13
  Bottom 0.305: 57.15,31.51 57.15,29.69 v56.67,29.21 | v62.55,29.21 61.59,28.26 61.59,24.45
RES\
  Bottom 0.305: 67.55,34.29 68.58,34.29 69.06,33.81 69.06,25.72 67.47,24.13 66.67,24.13
RX-LEVEL
  Bottom 0.2: 43.33,49.46 43.33,49.85 42.55,50.64 39.21,50.64 38.42,49.85 38.42,48.58 37.15,47.31 20.48,47.31 13.18,40.01 13.18,14.45 | 13.18,14.45 | 13.18,14.45 15.07,12.55 15.07,11.43 16.19,11.43 21.27,6.35 SV1.
RXD  (via drill 0.3 pad 0.61)
  Top 0.305: v54.93,27.94 70.64,27.94 v72.39,26.19
  Bottom 0.2: IC4.
  Bottom 0.305: 51.83,33.02 51.83,31.04 v54.93,27.94 | v72.39,26.19 73.82,24.77 IC4.
STB1  (via drill 0.3 pad 0.61)
  Top 0.305: v64.77,19.53 v48.26,19.53 v31.75,19.53
  Bottom 0.2: 64.77,21.54 | v64.77,19.53 64.77,21.54 | 48.26,21.54 | v48.26,19.53 48.26,21.54 | 31.75,21.54 | v31.75,19.53 31.75,21.54 | 64.77,21.54 | 64.77,21.54 64.77,22.54 65.25,23.02 67.47,23.02 70.8,26.35 70.8,28.1 72.23,29.53 75.56,29.53 76.04,30 76.04,36.51 75.41,37.15 75.41,40.64 75.09,40.96 70.17,40.96 69.85,40.64 67.55,40.64
STB2  (via drill 0.3 pad 0.61)
  Top 0.2: v58.42,45.72 54.77,42.07 50.01,42.07 v47.15,39.21
  Bottom 0.2: 58.42,47.23 | v58.42,45.72 58.42,47.23 | v47.15,39.21 45.88,37.94 45.88,34.61 46.12,34.37 46.68,34.37
T2OUT
  Bottom 0.2: 80.01,19.05 80.01,19.68 81.91,21.59 81.91,24.29 83.66,26.04 84.46,26.04 | 84.46,26.04 | 84.46,26.04 84.74,26.04
TX-LEVEL
  Bottom 0.2: R22. 57.78,50.32 56.99,51.12 39.05,51.12 37.94,50.01 37.94,48.74 36.99,47.78 20.32,47.78 12.7,40.16 12.7,14.29 14.13,12.86 14.13,10.64 14.45,10.32 16.19,10.32 16.34,10.17 16.34,9.21 17.78,9.21 23.18,3.81 24.77,3.81
TXD  (via drill 0.3 pad 0.61)
  Top 0.305: v55.88,28.57 71.12,28.57 v72.39,27.3
  Bottom 0.2: 78.9,26.04 | 78.9,26.04 79.22,26.04 | 76.19,25.72 76.2,25.73
  Bottom 0.305: 76.2,25.73 77.48,25.73 77.79,26.04 78.9,26.04 | 54.61,31.51 54.61,29.84 v55.88,28.57 | v72.39,27.3 73.98,25.72 76.19,25.72
VCC  (via drill 0.3 pad 0.61, 0.61 pad 1.02)
  Top 0.61: v91.44,25.4 84.14,25.4 76.04,17.3 v46.99,17.3 v23.81,17.3
  Bottom 0.61: R38. v23.8,17.29 v23.81,17.3 | v46.99,17.3 46.99,18.89 46.04,19.84 46.04,23.81 46.35,24.13 | 46.35,24.13 | 45.09,26.67 45.09,25.4 46.35,24.13
  Bottom 0.813: 88.11,36.83 89.53,36.83 91.44,34.92 v91.44,25.4
  Bottom 1.016: 95.25,18.85 95.25,20.64 93.98,21.91 93.98,24.77 92.07,24.77 v91.44,25.4
WR\
  Bottom 0.2: 62.87,26.83 | 62.87,26.67 62.87,26.83
  Bottom 0.305: 63.5,31.51 63.5,28.57 62.87,27.94 62.87,26.83
(copper drawn outside any net)
  shapes: Top circle x1

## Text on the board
Top: A
Dimension: 87,63 | 52,07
